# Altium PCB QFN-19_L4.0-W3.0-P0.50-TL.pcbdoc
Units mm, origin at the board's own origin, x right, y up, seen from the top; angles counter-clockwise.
Board outline 16.4 x 17.1 mm, 2 copper layers (Top Layer, Bottom Layer), stack 0 mm thick; 1 components, 0 nets, 19 pads, 0 vias.
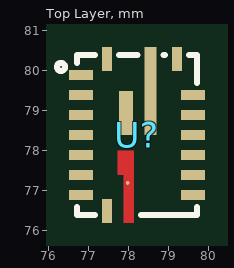
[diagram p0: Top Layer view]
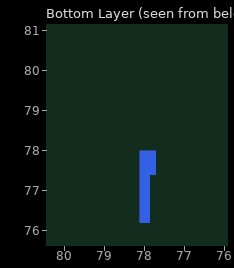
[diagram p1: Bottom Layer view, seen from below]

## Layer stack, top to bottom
Top Layer: signal copper (thickness not stored)
Bottom Layer: signal copper (thickness not stored)

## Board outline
86.25,69.85 69.85,69.85 69.85,86.95 86.25,86.95

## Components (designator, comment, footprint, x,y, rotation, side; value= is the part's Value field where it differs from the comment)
U? "" QFN-19_L4.0-W3.0-P0.50-TL 78.2,78.4 r0 top

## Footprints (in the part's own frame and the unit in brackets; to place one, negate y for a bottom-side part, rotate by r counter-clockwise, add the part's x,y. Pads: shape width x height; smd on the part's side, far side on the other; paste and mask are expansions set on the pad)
QFN-19_L4.0-W3.0-P0.50-TL [mm]
  rect 0.6x0.25 smd paste+0 mask+0.05: 1(-1.4,1.5) 2(-1.4,1) 3(-1.4,0.5) 4(-1.4,0) 5(-1.4,-0.5) 6(-1.4,-1) 7(-1.4,-1.5) 10(1.4,-1.5) 11(1.4,-1) 12(1.4,-0.5) 13(1.4,0) 14(1.4,0.5) 15(1.4,1)
  rect 0.25x0.6 smd paste+0 mask+0.05: 8(-0.75,-1.9) 16(1,1.9) 19(-0.75,1.9)
  round 0.092 smd: 9(-0.233,-1.2)
  rect 0.3x2.2 smd paste+0 mask+0.05: 17(0.34,1.1)
  rect 0.35x1.1 smd paste+0 mask+0.05: 18(-0.275,0.55)
  Top Layer region: -0.475,-1 -0.475,-0.4 -0.325,-0.4 -0.175,-0.4 -0.075,-0.4 -0.075,-2.2 -0.325,-2.2 -0.325,-1
  Bottom Layer region: -0.475,-1 -0.475,-0.4 -0.325,-0.4 -0.175,-0.4 -0.075,-0.4 -0.075,-2.2 -0.325,-2.2 -0.325,-1
  Multi-Layer region: -0.475,-1 -0.475,-0.4 -0.325,-0.4 -0.175,-0.4 -0.075,-0.4 -0.075,-2.2 -0.325,-2.2 -0.325,-1
  silkscreen extent -2,-2 1.5,2

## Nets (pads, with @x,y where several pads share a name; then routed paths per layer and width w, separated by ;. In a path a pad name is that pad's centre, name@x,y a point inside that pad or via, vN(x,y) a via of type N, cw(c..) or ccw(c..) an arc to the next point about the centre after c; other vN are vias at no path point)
pads on no net: U?.1 U?.2 U?.3 U?.4 U?.5 U?.6 U?.7 U?.8 U?.9 U?.10 U?.11 U?.12 U?.13 U?.14 U?.15 U?.16 U?.17 U?.18 U?.19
